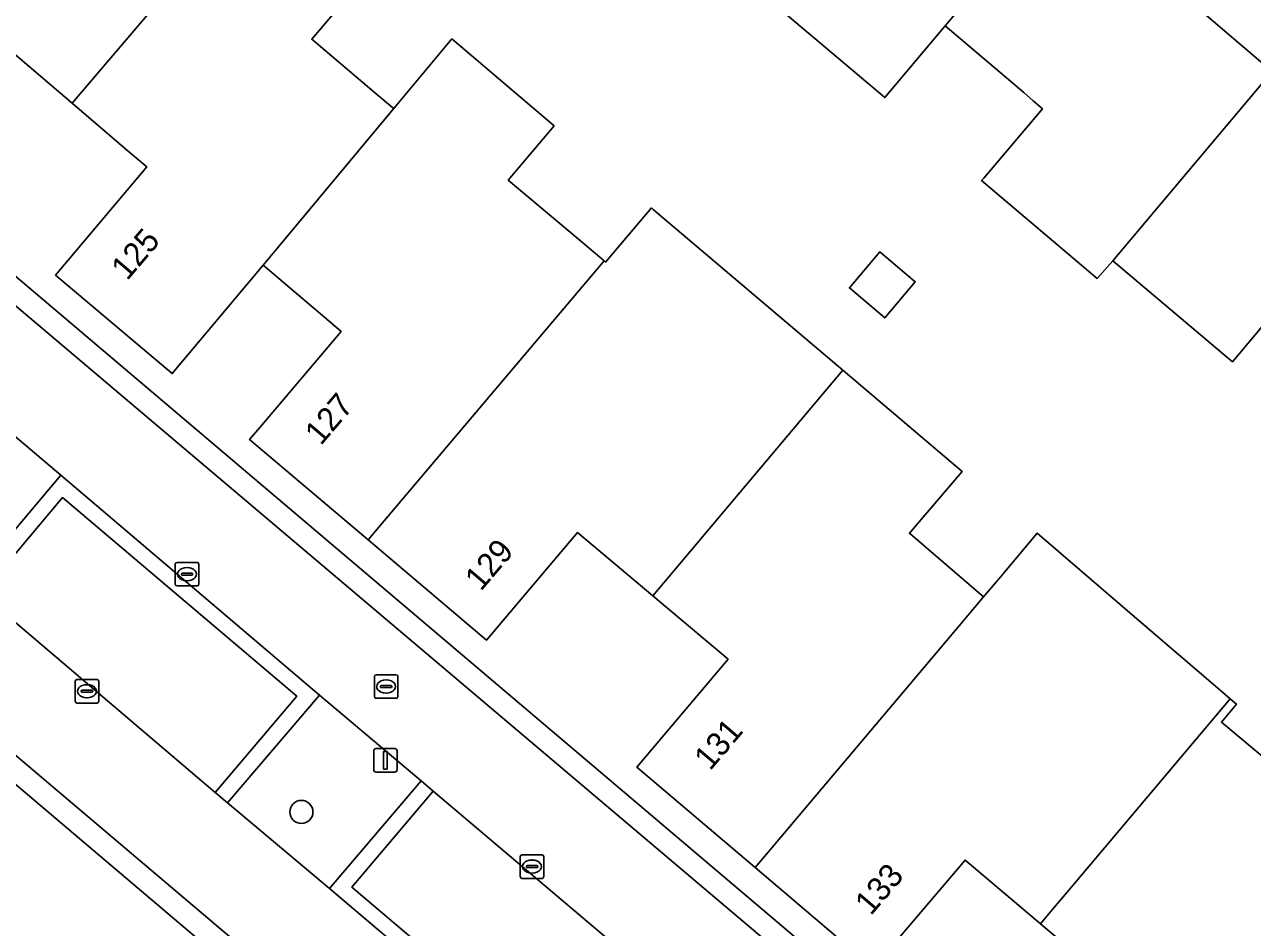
# Model space of a CAD drawing. Extents: x 156412 to 157779, y 382335 to 383768.
# Drawn here: x 156946.9 to 156999.1, y 382572.4 to 382610.8 of the extents above; entities that cross this region are included whole.
import ezdxf

# ---------------------------------------------------------------- set-up
doc = ezdxf.new("R2010")
doc.units = 0
for name, color, linetype in [('IMGEO_Boom', 7, 'Continuous'), ('IMGEO_Erf', 7, 'Continuous'), ('IMGEO_Groenvoorziening', 7, 'Continuous'), ('IMGEO_Kolk', 7, 'Continuous'), ('IMGEO_Lichtmast', 7, 'Continuous'), ('IMGEO_Pand', 7, 'Continuous'), ('IMGEO_Pand_nummerreeks', 7, 'Continuous'), ('IMGEO_Parkeervlak_open', 7, 'Continuous'), ('IMGEO_Rijbaan_lokaal_open', 7, 'Continuous'), ('IMGEO_Rioolput', 7, 'Continuous'), ('IMGEO_Voetpad_open', 7, 'Continuous')]:
    doc.layers.add(name, color=color, linetype=linetype)

msp = doc.modelspace()

# ---------------------------------------------------------------- linework, layer by layer
at = {"layer": 'IMGEO_Boom'}
msp.add_circle((156958.686, 382577.342), 0.489, dxfattribs=at)
at = {"layer": 'IMGEO_Erf'}
for points in [[(156961.62, 382613.099), (156959.125, 382610.154), (156961.859, 382607.838), (156962.548, 382607.254), (156962.603, 382607.207), (156965.078, 382610.169), (156969.416, 382606.474), (156967.472, 382604.176), (156970.54, 382601.589), (156971.54, 382600.745), (156971.605, 382600.691), (156973.558, 382602.992), (156973.629, 382602.932), (156981.688, 382596.096), (156986.745, 382591.806), (156984.508, 382589.18), (156987.657, 382586.477), (156988.334, 382587.266), (156989.939, 382589.181), (156994.47, 382585.294), (156997.705, 382582.519), (156998.139, 382582.147), (156998.401, 382581.923), (156997.759, 382581.156), (157001.838, 382577.741)], [(156996.558, 382611.649), (156999.924, 382608.789)], [(157000.161, 382598.747), (156998.232, 382596.46), (156993.145, 382600.75), (156992.484, 382600.002), (156987.576, 382604.152), (156987.666, 382604.254), (156987.673, 382604.263), (156990.16, 382607.208), (156989.764, 382607.541), (156989.371, 382607.888), (156986.03, 382610.723), (156983.464, 382607.677), (156979.683, 382610.874)], [(156982.982, 382570.712), (156977.954, 382574.98), (156972.931, 382579.245), (156976.808, 382583.824), (156973.613, 382586.519), (156970.417, 382589.213), (156966.552, 382584.643), (156961.52, 382588.901), (156956.487, 382593.158), (156957.002, 382593.767), (156960.368, 382597.747), (156959.862, 382598.178), (156957.727, 382599.997), (156957.336, 382600.33), (156957.056, 382600.568), (156953.201, 382595.955), (156948.246, 382600.143), (156952.125, 382604.733), (156951.247, 382605.481), (156948.947, 382607.439), (156945.768, 382610.144)], [(156985.096, 382551.062), (156984.751, 382551.362), (156982.188, 382548.489), (156956.652, 382569.938), (156926.325, 382595.645), (156936.95, 382608.202), (156992.775, 382560.898), (156990.241, 382557.869), (156990.622, 382557.547)], [(156993.281, 382569.886), (156990.076, 382572.59), (156987.046, 382575.146), (156986.871, 382575.294), (156983.552, 382571.384)]]:
    msp.add_lwpolyline(points, dxfattribs=at)
msp.add_lwpolyline([(156983.465, 382598.323), (156981.959, 382599.597), (156983.254, 382601.129), (156984.761, 382599.855)], close=True, dxfattribs=at)
at = {"layer": 'IMGEO_Groenvoorziening'}
for points in [[(156936.546, 382593.826), (156945.091, 382586.598), (156948.532, 382590.692), (156958.488, 382582.257), (156955.026, 382578.17), (156955.55, 382577.733), (156959.455, 382582.302), (156948.462, 382591.639), (156945.017, 382587.549), (156937.082, 382594.264), (156940.534, 382598.354)], [(156982.943, 382562.429), (156974.229, 382569.798), (156970.799, 382565.697), (156960.828, 382574.147), (156964.288, 382578.231), (156963.775, 382578.659), (156959.881, 382574.086), (156970.874, 382564.762), (156974.312, 382568.857), (156982.37, 382562.02), (156978.916, 382557.959)]]:
    msp.add_lwpolyline(points, dxfattribs=at)
at = {"layer": 'IMGEO_Kolk'}
for p, q in [((156953.327, 382587.013), (156953.327, 382587.865)), ((156953.402, 382587.939), (156954.254, 382587.939)), ((156953.815, 382587.719), (156953.84, 382587.719)), ((156954.328, 382587.865), (156954.328, 382587.013)), ((156953.586, 382587.433), (156953.586, 382587.445)), ((156954.024, 382587.396), (156953.626, 382587.396)), ((156953.629, 382587.482), (156954.027, 382587.482)), ((156954.07, 382587.445), (156954.07, 382587.433)), ((156954.254, 382586.939), (156953.402, 382586.939)), ((156953.838, 382587.159), (156953.813, 382587.159)), ((156949.078, 382582.041), (156949.078, 382582.893)), ((156949.153, 382582.967), (156950.005, 382582.967)), ((156949.337, 382582.461), (156949.337, 382582.473)), ((156949.38, 382582.51), (156949.778, 382582.51)), ((156949.566, 382582.747), (156949.591, 382582.747)), ((156949.821, 382582.473), (156949.821, 382582.461)), ((156950.079, 382582.893), (156950.079, 382582.041)), ((156950.005, 382581.967), (156949.153, 382581.967)), ((156949.775, 382582.424), (156949.377, 382582.424)), ((156949.589, 382582.187), (156949.564, 382582.187)), ((156967.981, 382574.595), (156967.981, 382575.447)), ((156968.056, 382575.521), (156968.908, 382575.521)), ((156968.469, 382575.301), (156968.494, 382575.301)), ((156968.982, 382575.447), (156968.982, 382574.595)), ((156968.24, 382575.015), (156968.24, 382575.027)), ((156968.678, 382574.978), (156968.28, 382574.978)), ((156968.283, 382575.064), (156968.681, 382575.064)), ((156968.492, 382574.741), (156968.467, 382574.741)), ((156968.724, 382575.027), (156968.724, 382575.015)), ((156968.908, 382574.521), (156968.056, 382574.521))]:
    msp.add_line(p, q, dxfattribs=at)
for points in [[(156953.327, 382587.013), (156953.327, 382587.865)], [(156953.402, 382587.939), (156954.254, 382587.939)], [(156954.328, 382587.865), (156954.328, 382587.013)], [(156954.254, 382586.939), (156953.402, 382586.939)], [(156949.078, 382582.041), (156949.078, 382582.893)], [(156949.153, 382582.967), (156950.005, 382582.967)], [(156950.079, 382582.893), (156950.079, 382582.041)], [(156950.005, 382581.967), (156949.153, 382581.967)], [(156967.981, 382574.595), (156967.981, 382575.447)], [(156968.056, 382575.521), (156968.908, 382575.521)], [(156968.982, 382575.447), (156968.982, 382574.595)], [(156968.908, 382574.521), (156968.056, 382574.521)]]:
    msp.add_lwpolyline(points, dxfattribs=at)
for centre, radius, start, end in [((156953.404, 382587.863), 0.0765, 91.552, 178.448), ((156953.404, 382587.863), 0.0765, 91.552, 178.448), ((156954.252, 382587.863), 0.0765, 1.552, 88.448), ((156954.252, 382587.863), 0.0765, 1.552, 88.448), ((156953.626, 382587.442), 0.0403, 85.8775, 175.7526), ((156953.623, 382587.432), 0.0366, 178.938, 274.7102), ((156954.027, 382587.439), 0.043, 264.8664, 352.4533), ((156954.031, 382587.444), 0.0386, 1.7309, 96.639), ((156953.404, 382587.015), 0.0765, 181.552, 268.448), ((156953.404, 382587.015), 0.0765, 181.552, 268.448), ((156954.252, 382587.015), 0.0765, 271.552, 358.448), ((156954.252, 382587.015), 0.0765, 271.552, 358.448), ((156949.155, 382582.891), 0.0765, 91.552, 178.448), ((156949.155, 382582.891), 0.0765, 91.552, 178.448), ((156949.377, 382582.47), 0.0403, 85.8775, 175.7526), ((156949.782, 382582.472), 0.0386, 1.7309, 96.639), ((156950.003, 382582.891), 0.0765, 1.552, 88.448), ((156950.003, 382582.891), 0.0765, 1.552, 88.448), ((156949.155, 382582.043), 0.0765, 181.552, 268.448), ((156949.155, 382582.043), 0.0765, 181.552, 268.448), ((156949.374, 382582.46), 0.0366, 178.938, 274.7102), ((156949.778, 382582.467), 0.043, 264.8664, 352.4533), ((156950.003, 382582.043), 0.0765, 271.552, 358.448), ((156950.003, 382582.043), 0.0765, 271.552, 358.448), ((156968.058, 382575.445), 0.0765, 91.552, 178.448), ((156968.058, 382575.445), 0.0765, 91.552, 178.448), ((156968.906, 382575.445), 0.0765, 1.552, 88.448), ((156968.906, 382575.445), 0.0765, 1.552, 88.448), ((156968.28, 382575.024), 0.0403, 85.8775, 175.7526), ((156968.277, 382575.014), 0.0366, 178.938, 274.7102), ((156968.681, 382575.021), 0.043, 264.8664, 352.4533), ((156968.685, 382575.026), 0.0386, 1.7309, 96.639), ((156968.058, 382574.597), 0.0765, 181.552, 268.448), ((156968.058, 382574.597), 0.0765, 181.552, 268.448), ((156968.906, 382574.597), 0.0765, 271.552, 358.448), ((156968.906, 382574.597), 0.0765, 271.552, 358.448)]:
    msp.add_arc(centre, radius, start, end, dxfattribs=at)
for centre, major_axis, ratio, start_param, end_param in [((156953.814, 382587.439), (-0.387, 0.002), 0.722429, 4.712389, 7.853982), ((156953.839, 382587.439), (-0.39, 0.002), 0.717154, 1.570796, 4.712389), ((156949.565, 382582.467), (-0.387, 0.002), 0.722429, 4.712389, 7.853982), ((156949.59, 382582.467), (-0.39, 0.002), 0.717154, 1.570796, 4.712389), ((156968.468, 382575.021), (-0.387, 0.002), 0.722429, 4.712389, 7.853982), ((156968.493, 382575.021), (-0.39, 0.002), 0.717154, 1.570796, 4.712389)]:
    msp.add_ellipse(centre, major_axis=major_axis, ratio=ratio, start_param=start_param, end_param=end_param, dxfattribs=at)
at = {"layer": 'IMGEO_Lichtmast'}
for p, q in [((156961.757, 382579.135), (156961.757, 382579.935)), ((156961.757, 382579.935), (156961.757, 382579.135)), ((156961.857, 382580.035), (156962.647, 382580.035)), ((156962.647, 382580.035), (156961.857, 382580.035)), ((156962.747, 382579.935), (156962.747, 382579.135)), ((156962.747, 382579.135), (156962.747, 382579.935)), ((156962.647, 382579.035), (156961.857, 382579.035)), ((156961.857, 382579.035), (156962.647, 382579.035))]:
    msp.add_line(p, q, dxfattribs=at)
msp.add_lwpolyline([(156962.177, 382579.91), (156962.327, 382579.91), (156962.327, 382579.16), (156962.177, 382579.16), (156962.177, 382579.91)], dxfattribs=at)
for centre, start, end in [((156961.857, 382579.935), 90, 180), ((156961.857, 382579.935), 90, 180), ((156962.647, 382579.935), 0, 90), ((156962.647, 382579.935), 360, 90), ((156961.857, 382579.135), 180, 270), ((156961.857, 382579.135), 180, 270), ((156962.647, 382579.135), 270, 0), ((156962.647, 382579.135), 270, 0)]:
    msp.add_arc(centre, 0.1, start, end, dxfattribs=at)
at = {"layer": 'IMGEO_Pand'}
for points in [[(156994.788, 382621.028), (156993.911, 382621.774), (156989.628, 382625.414), (156989.479, 382625.241), (156985.688, 382620.85), (156982.459, 382623.598), (156975, 382614.833), (156975.065, 382614.778), (156979.683, 382610.874), (156983.464, 382607.677), (156986.03, 382610.723)], [(156957.056, 382616.966), (156952.208, 382621.074), (156950.268, 382618.785), (156947.027, 382621.512), (156936.982, 382609.714), (156941.846, 382605.59), (156944.084, 382608.188), (156945.768, 382610.144), (156948.947, 382607.439)], [(156994.788, 382621.028), (156986.03, 382610.723), (156989.371, 382607.888), (156989.764, 382607.541), (156990.16, 382607.208), (156987.673, 382604.263), (156987.666, 382604.254), (156987.576, 382604.152), (156992.484, 382600.002), (156993.145, 382600.75), (156999.924, 382608.789), (156996.558, 382611.649), (157000.288, 382616.038), (157000.444, 382616.221), (156994.906, 382620.928)], [(156962.603, 382607.207), (156962.548, 382607.254), (156961.859, 382607.838), (156959.125, 382610.154), (156961.62, 382613.099), (156957.056, 382616.966), (156948.947, 382607.439), (156951.247, 382605.481), (156952.125, 382604.733), (156948.246, 382600.143), (156953.201, 382595.955), (156957.056, 382600.568), (156957.55, 382601.159)], [(157011.825, 382606.587), (157011.288, 382607.044), (157006.937, 382610.746), (157006.762, 382610.541), (157003.02, 382606.157), (156999.924, 382608.789), (156993.145, 382600.75), (156998.232, 382596.46), (157000.161, 382598.747), (157000.331, 382598.599), (157003.061, 382596.286)], [(156971.54, 382600.745), (156970.54, 382601.589), (156967.472, 382604.176), (156969.416, 382606.474), (156965.078, 382610.169), (156962.603, 382607.207), (156957.55, 382601.159), (156957.056, 382600.568), (156957.336, 382600.33), (156957.727, 382599.997), (156959.862, 382598.178), (156960.368, 382597.747), (156957.002, 382593.767), (156956.487, 382593.158), (156961.52, 382588.901), (156962.042, 382589.518)], [(156981.688, 382596.096), (156973.629, 382602.932), (156973.558, 382602.992), (156971.605, 382600.691), (156971.54, 382600.745), (156962.042, 382589.518), (156961.52, 382588.901), (156966.552, 382584.643), (156970.417, 382589.213), (156973.613, 382586.519)], [(156981.959, 382599.597), (156983.465, 382598.323), (156984.761, 382599.855), (156983.254, 382601.129)], [(156987.657, 382586.477), (156984.508, 382589.18), (156986.745, 382591.806), (156981.688, 382596.096), (156973.613, 382586.519), (156976.808, 382583.824), (156972.931, 382579.245), (156977.954, 382574.98), (156978.508, 382575.636), (156986.622, 382585.251)], [(156998.139, 382582.147), (156997.705, 382582.519), (156994.47, 382585.294), (156989.939, 382589.181), (156988.334, 382587.266), (156987.657, 382586.477), (156986.622, 382585.251), (156978.508, 382575.636), (156977.954, 382574.98), (156982.982, 382570.712), (156983.552, 382571.384), (156986.871, 382575.294), (156987.046, 382575.146), (156990.076, 382572.59), (156990.633, 382573.251), (156991.212, 382573.937)], [(157006.182, 382575.348), (157002.487, 382578.502), (157001.883, 382577.793), (157001.838, 382577.741), (156997.759, 382581.156), (156998.401, 382581.923), (156998.139, 382582.147), (156991.212, 382573.937), (156990.633, 382573.251), (156990.076, 382572.59), (156993.281, 382569.886), (156989.394, 382565.302), (156994.273, 382561.165)]]:
    msp.add_lwpolyline(points, close=True, dxfattribs=at)
at = {"layer": 'IMGEO_Parkeervlak_open'}
for points in [[(156940.534, 382598.354), (156937.082, 382594.264), (156945.017, 382587.549), (156948.462, 382591.639)], [(156948.532, 382590.692), (156945.091, 382586.598), (156955.026, 382578.17), (156958.488, 382582.257)], [(156963.775, 382578.659), (156959.455, 382582.302), (156955.55, 382577.733), (156959.881, 382574.086)], [(156964.288, 382578.231), (156960.828, 382574.147), (156970.799, 382565.697), (156974.229, 382569.798)]]:
    msp.add_lwpolyline(points, close=True, dxfattribs=at)
at = {"layer": 'IMGEO_Rijbaan_lokaal_open'}
for points in [[(156989.555, 382557.259), (156988.981, 382557.799), (156991.519, 382560.783), (156937.011, 382606.884), (156927.619, 382595.781), (156982.077, 382549.644), (156984.601, 382552.665), (156985.195, 382552.172)], [(156940.534, 382598.354), (156948.462, 382591.639), (156959.455, 382582.302), (156963.775, 382578.659), (156964.288, 382578.231), (156974.229, 382569.798), (156982.943, 382562.429)], [(156978.916, 382557.959), (156970.874, 382564.762), (156959.881, 382574.086), (156955.55, 382577.733), (156955.026, 382578.17), (156945.091, 382586.598), (156936.546, 382593.826)]]:
    msp.add_lwpolyline(points, dxfattribs=at)
at = {"layer": 'IMGEO_Rioolput'}
for p, q in [((156961.783, 382582.241), (156961.783, 382583.093)), ((156961.858, 382583.167), (156962.71, 382583.167)), ((156962.784, 382583.093), (156962.784, 382582.241)), ((156962.042, 382582.661), (156962.042, 382582.673)), ((156962.48, 382582.624), (156962.082, 382582.624)), ((156962.085, 382582.71), (156962.483, 382582.71)), ((156962.271, 382582.947), (156962.296, 382582.947)), ((156962.526, 382582.673), (156962.526, 382582.661)), ((156962.71, 382582.167), (156961.858, 382582.167)), ((156962.294, 382582.387), (156962.269, 382582.387))]:
    msp.add_line(p, q, dxfattribs=at)
for points in [[(156961.783, 382582.241), (156961.783, 382583.093)], [(156961.858, 382583.167), (156962.71, 382583.167)], [(156962.784, 382583.093), (156962.784, 382582.241)], [(156962.71, 382582.167), (156961.858, 382582.167)]]:
    msp.add_lwpolyline(points, dxfattribs=at)
for centre, radius, start, end in [((156961.86, 382583.091), 0.0765, 91.552, 178.448), ((156961.86, 382583.091), 0.0765, 91.552, 178.448), ((156962.708, 382583.091), 0.0765, 1.552, 88.448), ((156962.708, 382583.091), 0.0765, 1.552, 88.448), ((156962.082, 382582.67), 0.0403, 85.8775, 175.7526), ((156962.079, 382582.66), 0.0366, 178.938, 274.7102), ((156962.483, 382582.667), 0.043, 264.8664, 352.4533), ((156962.487, 382582.672), 0.0386, 1.7309, 96.639), ((156961.86, 382582.243), 0.0765, 181.552, 268.448), ((156961.86, 382582.243), 0.0765, 181.552, 268.448), ((156962.708, 382582.243), 0.0765, 271.552, 358.448), ((156962.708, 382582.243), 0.0765, 271.552, 358.448)]:
    msp.add_arc(centre, radius, start, end, dxfattribs=at)
for centre, major_axis, ratio, start_param, end_param in [((156962.27, 382582.667), (-0.387, 0.002), 0.722429, 4.712389, 7.853982), ((156962.295, 382582.667), (-0.39, 0.002), 0.717154, 1.570796, 4.712389)]:
    msp.add_ellipse(centre, major_axis=major_axis, ratio=ratio, start_param=start_param, end_param=end_param, dxfattribs=at)
at = {"layer": 'IMGEO_Voetpad_open'}
for points in [[(156990.622, 382557.547), (156990.241, 382557.869), (156992.775, 382560.898), (156936.95, 382608.202), (156926.325, 382595.645), (156956.652, 382569.938), (156982.188, 382548.489), (156984.751, 382551.362), (156985.096, 382551.062)], [(156985.195, 382552.172), (156984.601, 382552.665), (156982.077, 382549.644), (156927.619, 382595.781), (156937.011, 382606.884)], [(156937.011, 382606.884), (156991.519, 382560.783), (156988.981, 382557.799), (156989.555, 382557.259)]]:
    msp.add_lwpolyline(points, dxfattribs=at)

# ---------------------------------------------------------------- texts
at = {"layer": 'IMGEO_Pand_nummerreeks'}
for s, rotation, p in [('125', 49.601, (156951.285, 382599.873)), ('127', 49.578, (156959.51, 382592.869)), ('129', 49.578, (156966.307, 382586.684)), ('131', 49.5494, (156976.044, 382579.061)), ('133', 49.4806, (156982.871, 382572.907))]:
    msp.add_text(s, height=1, rotation=rotation, dxfattribs=at).set_placement(p)

doc.saveas('drawing.dxf')
